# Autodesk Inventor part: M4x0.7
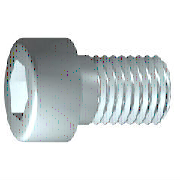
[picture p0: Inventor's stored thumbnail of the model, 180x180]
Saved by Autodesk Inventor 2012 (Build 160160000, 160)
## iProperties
Created: 2009-02
Part Number: M4x0.7
Material: 강, 연강
Description: 6각머리 태핑 나사
Document SubType Name: Modeling
Standard: KS B 1003
Standards Organization: KS
Language: ko-KR
Size Designation: M 4 x 12
Categories: <MemberInstance><Categories><Category DisplayName="조임쇠" InternalName="e4da775c-781d-43d5-af7c-5136215cf5a6" Mnemonic="FSTN"><Category DisplayName="볼트" InternalN
Density: 1 g/cm^3
Checked By: KYOUNG IL JANG
Vendor: CBT Solutions
Designer: KYOUNG IL JANG
Manager: KYOUNG IL JANG
Company: 한국ATC센터
IsCustomPart: 0
Author: KYOUNG IL JANG
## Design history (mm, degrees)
workplane "Work Plane1"
fillet "Fillet2" dims "d30" = 0.1 (= R)
revolve "본체" stored, may be unused: angle "d10" = 90 deg
sketch "스케치2"
  geometry: L1 (0, -4.9)-(0, 4.9) reference; L2 (-4.9, 0)-(4.9, 0) reference; L3 (1.732, 0)-(0.866, -1.5); L4 (0.866, -1.5)-(-0.866, -1.5); L5 (-0.866, -1.5)-(-1.732, 0); L6 (-1.732, 0)-(-0.866, 1.5); L7 (-0.866, 1.5)-(0.866, 1.5); L8 (0.866, 1.5)-(1.732, 0); 2 further points
  constraints: 12 end point, 1 coincident, 1 horizontal alignment, 1 point on line, 12 other
extrude "슬롯" join sketch "스케치2" stored distance "d11" = 10; taper "d12" = 0 deg
body "Solid1"
fillet "모깎기1" dims "d17" = 0.4 (= RR)
feature "스레드" dims "d13" = 10.25 (= GEL), "d14" = 0
chamfer "모따기1" distance "d15" = 0.42941 (= -0.5 x SPD + 0.5 x GD); stored, may be unused: second distance "d16" = 0.42941 (= GUL), angle "d27" = 45 deg
sketch "스케치1"
  geometry: L1 (-1, 0)-(12, 0); L2 (12, 0)-(12, 2); L3 (12, 2)-(1.75, 2); L4 (1.75, 2)-(1.32, 2); L5 (1.32, 2)-(0, 2); L6 (0, 2)-(0, 3.5); L7 (0, 3.5)-(-4, 3.5); L8 (-4, 3.5)-(-4, 1.732); L9 (-4, 1.732)-(-2, 1.732); L10 (-2, 1.732)-(-1, 0); L11 (-7.2, 0)-(15.2, 0) reference; L12 (0, -0.7)-(0, 4.2) reference; L13 (1.75, 2)-(0, 2)
  constraints: 22 end point, 6 parallel, 2 collinear, 2 perpendicular, 1 horizontal, 1 point on line
  dimensions: "d1" = 10.25 distance from line of L3.end L2 (= GEL); "d2" = 0.42952 distance of L4.end L3.end (computed from GAL); "d3" = 4 distance between parallel lines of L8 L6 (= KOH); "d4" = 2 distance of L8.end L9.end (= INTI); "d5" = 60 deg angle of L10 L1; "d6" = 4 diameter of L3 L1 (= GD); "d7" = 4 diameter of L5 L1 (= BDM); "d8" = 3.4641 diameter of L9 L1 (= 1.1547 x SW); "d9" = 7 diameter of L7 L1 (= KOD); "d26" = 12 distance between parallel lines of L12 L2 (= NLG)
other parameters: "GD" = 4 (= NND) [user parameter; used in 2 equation terms], "NLG" = 12 [user parameter; used in 1 equation term], "GEL" = 10.25 [user parameter; used in 2 equation terms], "KOD" = 7 [user parameter; used in 1 equation term], "KOH" = 4 [user parameter; used in 1 equation term], "INTI" = 2 [user parameter; used in 1 equation term], "GAL" = 0.42941 (= 0.61345 x PTC) [user parameter; used in 1 equation term], "GUL" = 0.42941 (= 0.61345 x PTC) [user parameter; used in 1 equation term], "BDM" = 4 (= NND) [user parameter; used in 1 equation term], "SW" = 3 [user parameter; used in 2 equation terms], "RR" = 0.4 [user parameter; used in 1 equation term], "SPD" = 3.14117 (= NND - 1.2269 x PTC) [user parameter; used in 1 equation term], "d19" = 0, "d28" = 0, "d29" = 0, "R" = 0.1 [user parameter; used in 1 equation term], "PHH" = 0.2 [user parameter], "GD1" = 3.14117 (= THREADDIA - 1.2269 x PTC) [user parameter], "THREADDIA" = 4 [user parameter; used in 1 equation term], "FAWI" = 45 deg [user parameter], "TPU" = 14.28571 (computed from PTC) [user parameter], "PTC" = 0.7 [user parameter; used in 5 equation terms], "NND" = 4 [user parameter; used in 3 equation terms], "TOA" = 30 deg [user parameter], "E0" = 3.465 (= 1.155 x SW) [user parameter]
